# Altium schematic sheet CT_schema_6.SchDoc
size 278 x 170 mm
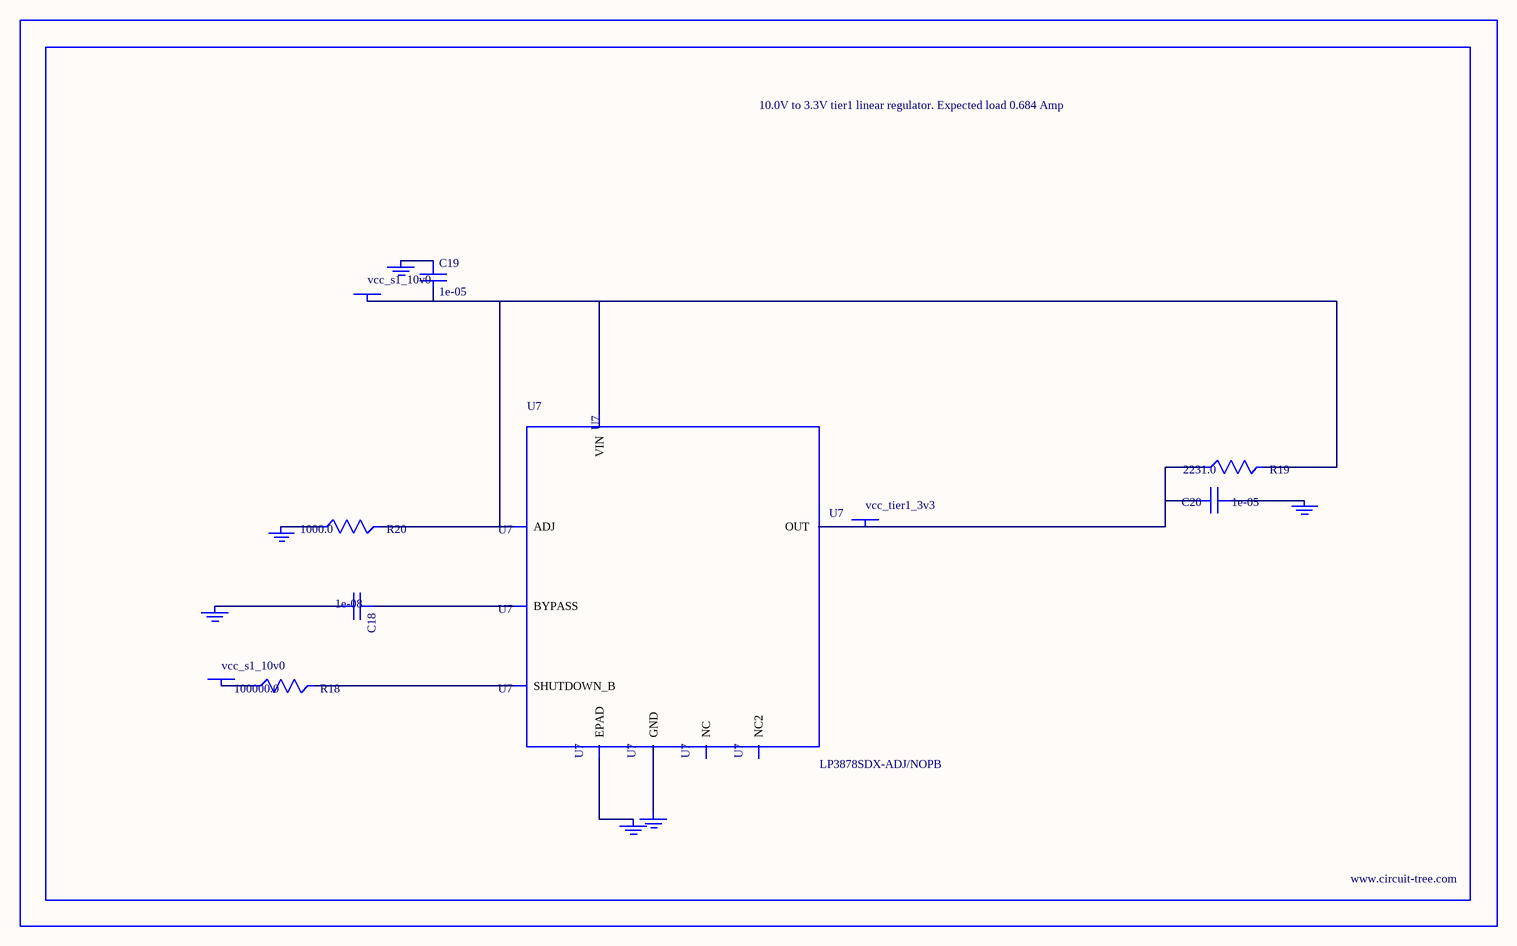
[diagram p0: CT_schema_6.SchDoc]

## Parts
BORDER5  (no value)
C18  1e-08  [C0402]
C19  1e-05  [C1206]
C20  1e-05  [C1210]
GND_INSTANCE_5_0  (no value)
GND_INSTANCE_5_1  (no value)
GND_INSTANCE_5_2  (no value)
GND_INSTANCE_5_3  (no value)
GND_INSTANCE_5_4  (no value)
GND_INSTANCE_5_5  (no value)
POWER_INSTANCE_5_0  vcc_s1_10v0
POWER_INSTANCE_5_1  vcc_s1_10v0
POWER_INSTANCE_5_2  vcc_tier1_3v3
R18  100000.0  [R0603]
R19  2231.0  [R0603]
R20  1000.0  [R0603]
U7  LP3878SDX-ADJ/NOPB  [WSON-8]

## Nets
NetC18_1: C18.1 U7.1(BYPASS)
NetC18_2: C18.2 GND_INSTANCE_5_0.0(GND)
NetC19_1: C19.1 GND_INSTANCE_5_1.0(GND)
NetC19_2: C19.2 POWER_INSTANCE_5_0.0(PWR) R19.2 R20.2 U7.4(VIN) U7.6(ADJ)
NetC20_1: C20.1 GND_INSTANCE_5_2.0(GND)
NetC20_2: C20.2 POWER_INSTANCE_5_2.0(PWR) R19.1 U7.5(OUT)
NetGND_INSTANCE_5_3_0: GND_INSTANCE_5_3.0(GND) R20.1
NetGND_INSTANCE_5_4_0: GND_INSTANCE_5_4.0(GND) U7.PAD(EPAD)
NetGND_INSTANCE_5_5_0: GND_INSTANCE_5_5.0(GND) U7.3(GND)
NetPOWER_INSTANCE_5_1_0: POWER_INSTANCE_5_1.0(PWR) R18.1
NetR18_2: R18.2 U7.8(SHUTDOWN_B)

Not connected (* = marked no-connect by the designer): U7 2(NC) 7(NC2)

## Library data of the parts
BORDER5 = BORDER_PAGE5
C18 = C0402C103K3RAC
C19 = C1206C106K3RACTU
C20 = GRM32DR61E106MA12L
GND_INSTANCE_5_0-GND_INSTANCE_5_5 = GND
POWER_INSTANCE_5_0-POWER_INSTANCE_5_2 = PWR
R18 = RC0603JR-07100KL
R19 = R19
R20 = RC0603JR-071KL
